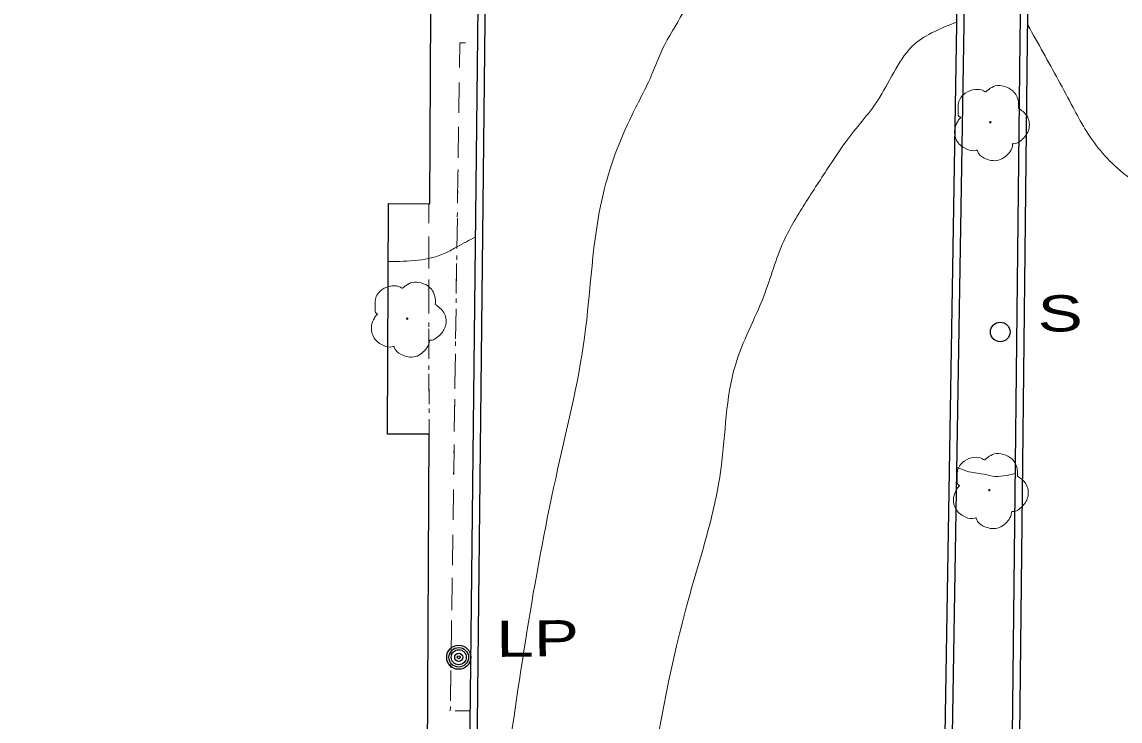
# Model space of a CAD drawing. Extents: x 2362213 to 2366494, y 6968794 to 6978110.
# Drawn here: x 2364097.3 to 2364243, y 6974757.5 to 6974850.3 of the extents above; entities that cross this region are included whole.
import ezdxf

# ---------------------------------------------------------------- set-up
doc = ezdxf.new("R2010")
doc.units = 0
doc.header["$LTSCALE"] = 1.9
doc.linetypes.add('DOTTED', pattern=[1.5, 0.3, -1.2])
for name, color, linetype, lineweight in [('11', 7, 'Continuous', 25), ('13', 7, 'Continuous', 13), ('2', 7, 'Continuous', 25), ('20', 7, 'Continuous', 25), ('21', 7, 'Continuous', 25), ('29', 7, 'Continuous', 13), ('35', 7, 'Continuous', 13)]:
    doc.layers.add(name, color=color, linetype=linetype, lineweight=lineweight)

msp = doc.modelspace()

# ---------------------------------------------------------------- linework, layer by layer
at = {"layer": '11'}
msp.add_lwpolyline([(2364144.499, 6974705.543), (2364144.65, 6974735.807), (2364151.03, 6974735.778), (2364151.301, 6974795.572), (2364145.771, 6974795.6), (2364145.92, 6974826.173), (2364151.409, 6974826.146), (2364152.012, 6974945.557), (2364147.142, 6974945.58), (2364147.239, 6974965.852), (2364153.059, 6974965.828), (2364153.569, 6975085.578), (2364148.939, 6975085.594), (2364149.041, 6975115.776), (2364154.952, 6975115.753), (2364155.191, 6975175.679), (2364150.001, 6975175.699), (2364150.119, 6975205.342), (2364048.33, 6975205.742), (2364046.369, 6974705.929)], close=True, dxfattribs=at)
at = {"layer": '13'}
for p, q in [((2364155.255, 6974838.232), (2364155.316, 6974842.233)), ((2364155.172, 6974832.232), (2364155.224, 6974836.231)), ((2364155.089, 6974826.231), (2364155.141, 6974830.231)), ((2364151.274, 6974823.574), (2364151.269, 6974826.144)), ((2364154.996, 6974820.229), (2364155.058, 6974824.23)), ((2364151.281, 6974817.573), (2364151.273, 6974821.573)), ((2364154.913, 6974814.228), (2364154.965, 6974818.228)), ((2364151.288, 6974811.574), (2364151.28, 6974815.573)), ((2364154.83, 6974808.227), (2364154.882, 6974812.228)), ((2364151.295, 6974805.574), (2364151.287, 6974809.574)), ((2364154.747, 6974802.226), (2364154.799, 6974806.227)), ((2364151.302, 6974799.573), (2364151.294, 6974803.574)), ((2364154.655, 6974796.224), (2364154.716, 6974800.226)), ((2364151.301, 6974795.572), (2364151.302, 6974797.572)), ((2364154.572, 6974790.223), (2364154.624, 6974794.224)), ((2364154.489, 6974784.223), (2364154.541, 6974788.224)), ((2364154.406, 6974778.222), (2364154.458, 6974782.223)), ((2364154.313, 6974772.22), (2364154.375, 6974776.221)), ((2364154.23, 6974766.22), (2364154.282, 6974770.219)), ((2364154.137, 6974760.219), (2364154.199, 6974764.219)), ((2364156.77, 6974758.864), (2364154.77, 6974758.865))]:
    msp.add_line(p, q, dxfattribs=at)
at = {"layer": '13', "linetype": 'DOTTED'}
msp.add_line((2364151.301, 6974795.572), (2364151.269, 6974826.144), dxfattribs=at)
msp.add_lwpolyline([(2364156.77, 6974758.864), (2364154.12, 6974758.868), (2364155.386, 6974847.495), (2364157.756, 6974847.547)], dxfattribs=at)
at = {"layer": '13'}
msp.add_lwpolyline([(2364155.347, 6974844.234), (2364155.386, 6974847.495), (2364156.126, 6974847.512)], dxfattribs=at)
at = {"layer": '2'}
for points in [[(2364221.858, 6974924.261), (2364221.316, 6974849.932), (2364219.62, 6974747.611)], [(2364222.818, 6974924.25), (2364222.276, 6974849.922), (2364220.581, 6974747.59)], [(2364228.65, 6974747.647), (2364229.767, 6974847.793), (2364230.8, 6974923.046)], [(2364229.611, 6974747.636), (2364230.727, 6974847.782), (2364231.761, 6974923.035)], [(2364156.663, 6974749.151), (2364158.43, 6974908.005), (2364171.521, 6974909.05)], [(2364157.623, 6974749.14), (2364159.379, 6974907.114), (2364171.6, 6974908.091)]]:
    msp.add_lwpolyline(points, dxfattribs=at)
at = {"layer": '20'}
for radius in [1.6, 1.3, 1, 0.539, 0.192]:
    msp.add_circle((2364155.243, 6974765.979), radius, dxfattribs=at)
at = {"layer": '21'}
msp.add_circle((2364227.105, 6974809.145), 1.3, dxfattribs=at)
at = {"layer": '29'}
for centre in [(2364225.8, 6974836.974), (2364148.404, 6974810.916), (2364225.655, 6974788.151)]:
    msp.add_circle(centre, 0.1, dxfattribs=at)
for points in [[(2364221.834, 6974837.546), (2364221.854, 6974837.556), (2364221.773, 6974837.625), (2364221.537, 6974838.253), (2364221.575, 6974839.533), (2364222.463, 6974840.832), (2364223.768, 6974841.314), (2364224.89, 6974841.125), (2364225.121, 6974840.997), (2364225.191, 6974840.998), (2364225.241, 6974841.038), (2364225.588, 6974841.332), (2364226.454, 6974841.78), (2364227.665, 6974841.712), (2364228.78, 6974841.122), (2364229.514, 6974839.699), (2364229.522, 6974838.839)], [(2364229.512, 6974838.859), (2364230.652, 6974837.8), (2364230.937, 6974836.213), (2364230.23, 6974834.887), (2364229.575, 6974834.34), (2364228.907, 6974834.124), (2364228.757, 6974834.113), (2364228.738, 6974834.002), (2364228.417, 6974833.099), (2364226.878, 6974831.935), (2364224.985, 6974832.217), (2364224.086, 6974833.158), (2364224.015, 6974833.287), (2364223.895, 6974833.266), (2364222.684, 6974833.385), (2364221.414, 6974834.383), (2364221.069, 6974836.019), (2364221.439, 6974837.042), (2364221.765, 6974837.485), (2364221.834, 6974837.536)], [(2364144.44, 6974811.489), (2364144.46, 6974811.499), (2364144.379, 6974811.568), (2364144.143, 6974812.196), (2364144.181, 6974813.475), (2364145.068, 6974814.774), (2364146.373, 6974815.256), (2364147.495, 6974815.067), (2364147.726, 6974814.939), (2364147.796, 6974814.94), (2364147.846, 6974814.98), (2364148.193, 6974815.274), (2364149.059, 6974815.722), (2364150.269, 6974815.653), (2364151.385, 6974815.064), (2364152.119, 6974813.641), (2364152.127, 6974812.781)], [(2364152.117, 6974812.801), (2364153.257, 6974811.743), (2364153.542, 6974810.155), (2364152.834, 6974808.828), (2364152.18, 6974808.282), (2364151.512, 6974808.066), (2364151.362, 6974808.054), (2364151.343, 6974807.944), (2364151.021, 6974807.041), (2364149.482, 6974805.876), (2364147.59, 6974806.158), (2364146.691, 6974807.1), (2364146.619, 6974807.229), (2364146.5, 6974807.208), (2364145.289, 6974807.327), (2364144.02, 6974808.325), (2364143.674, 6974809.961), (2364144.044, 6974810.985), (2364144.37, 6974811.428), (2364144.44, 6974811.479)], [(2364221.689, 6974788.723), (2364221.709, 6974788.733), (2364221.628, 6974788.803), (2364221.392, 6974789.43), (2364221.43, 6974790.71), (2364222.318, 6974792.008), (2364223.623, 6974792.491), (2364224.745, 6974792.301), (2364224.976, 6974792.174), (2364225.046, 6974792.174), (2364225.096, 6974792.215), (2364225.443, 6974792.508), (2364226.309, 6974792.956), (2364227.52, 6974792.888), (2364228.635, 6974792.299), (2364229.369, 6974790.875), (2364229.377, 6974790.016)], [(2364229.367, 6974790.036), (2364230.507, 6974788.977), (2364230.792, 6974787.39), (2364230.085, 6974786.063), (2364229.43, 6974785.517), (2364228.762, 6974785.3), (2364228.612, 6974785.289), (2364228.593, 6974785.179), (2364228.272, 6974784.276), (2364226.733, 6974783.111), (2364224.84, 6974783.393), (2364223.941, 6974784.334), (2364223.87, 6974784.464), (2364223.75, 6974784.443), (2364222.539, 6974784.561), (2364221.269, 6974785.559), (2364220.923, 6974787.196), (2364221.294, 6974788.219), (2364221.62, 6974788.663), (2364221.689, 6974788.713)]]:
    msp.add_spline(points, degree=3, dxfattribs=at)
at = {"layer": '35'}
for points in [[(2364272.528, 6974950.795), (2364271.344, 6974949.133), (2364269.528, 6974946.526), (2364268.177, 6974942.503), (2364266.551, 6974935.757), (2364264.265, 6974930.034), (2364262.423, 6974927.077), (2364260.748, 6974923.531), (2364257.996, 6974921.615), (2364254.304, 6974920.74), (2364250.977, 6974921.418), (2364248.697, 6974923.496), (2364245.644, 6974927.978), (2364242.636, 6974932.008), (2364238.33, 6974939.919), (2364236.61, 6974944.172), (2364232.311, 6974949.302), (2364230.281, 6974951.282), (2364228.527, 6974951.776), (2364224.209, 6974952.585), (2364222.386, 6974952.896), (2364217.238, 6974952.638), (2364212.165, 6974948.86), (2364208.946, 6974939.099), (2364206.079, 6974928.301), (2364204.041, 6974924.951), (2364200.347, 6974914.856), (2364194.854, 6974886.791), (2364193.089, 6974882.055), (2364191.668, 6974878.001), (2364190.081, 6974870.386), (2364189.236, 6974861.406), (2364187.067, 6974855.957), (2364184.97, 6974851.456), (2364182.295, 6974846.691), (2364180.887, 6974843.336), (2364178.238, 6974837.941), (2364174.389, 6974827.385), (2364171.929, 6974808.39), (2364168.108, 6974789.712), (2364161.255, 6974748.895)], [(2364221.323, 6974850.253), (2364218.315, 6974848.984), (2364215.77, 6974847.36), (2364211.128, 6974840.294), (2364206.88, 6974834.734), (2364204.7, 6974831.583), (2364201.369, 6974826.451), (2364198.369, 6974821.182), (2364195.718, 6974813.906), (2364191.956, 6974804.751), (2364190.066, 6974791.131), (2364188.48, 6974783.347), (2364185.769, 6974773.809), (2364180.352, 6974748.287)], [(2364271.43, 6974843.468), (2364269.598, 6974842.661), (2364266.691, 6974841.263), (2364264.695, 6974839.724), (2364261.183, 6974835.901), (2364257.597, 6974832.287), (2364255.152, 6974829.584), (2364252.104, 6974828.215), (2364247.095, 6974828.137), (2364243.002, 6974830.558), (2364238.34, 6974836.094), (2364236.773, 6974838.918), (2364232.803, 6974846.222), (2364230.757, 6974849.852)], [(2364157.472, 6974821.743), (2364155.044, 6974820.459), (2364153.512, 6974819.634), (2364149.851, 6974818.659), (2364145.883, 6974818.492)], [(2364229.124, 6974790.353), (2364226.067, 6974790.015), (2364224.594, 6974790.34), (2364223.512, 6974790.48), (2364221.305, 6974791.199)]]:
    msp.add_spline(points, degree=3, dxfattribs=at)

# ---------------------------------------------------------------- texts
at = {"layer": '20', "width": 1.4}
msp.add_text('  LP', height=4.8, rotation=0.546, dxfattribs=at).set_placement((2364155.243, 6974765.979))
at = {"layer": '21', "width": 1.4}
msp.add_text('  S', height=4.8, rotation=0.546, dxfattribs=at).set_placement((2364227.095, 6974809.136))

doc.saveas('drawing.dxf')
